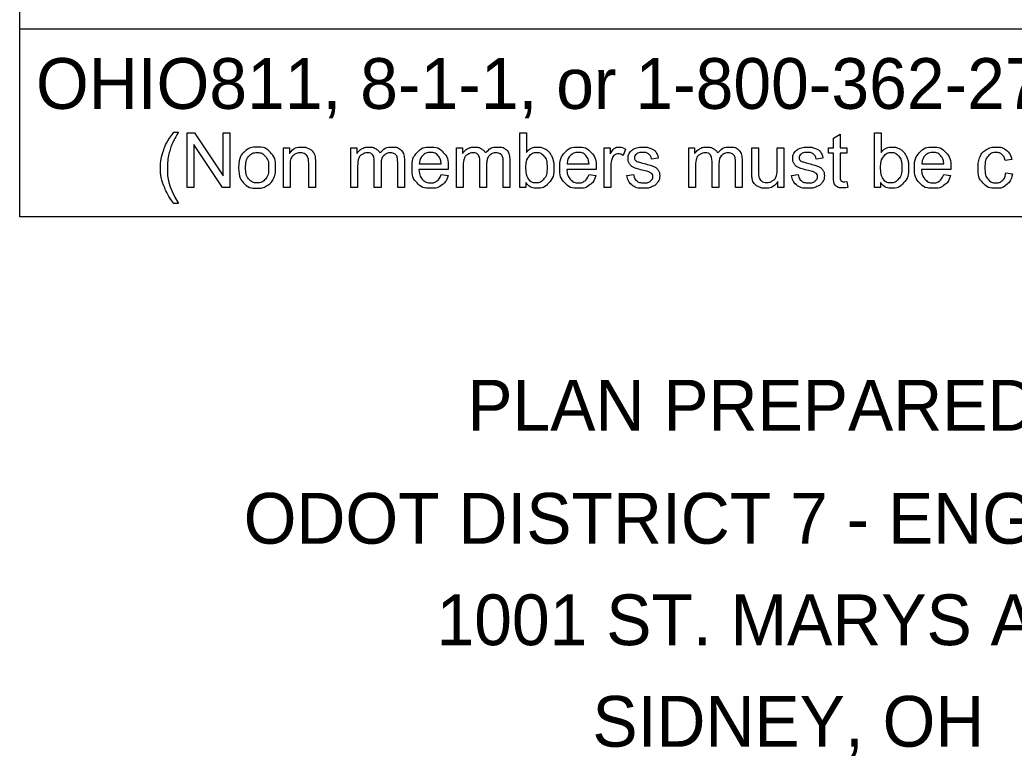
# Model space of a CAD drawing. Extents: x -31.7 to 34, y 0 to 22.
# Drawn here: x -30.869 to -28.125, y 0.655 to 2.686 of the extents above; entities that cross this region are included whole.
import ezdxf

# ---------------------------------------------------------------- set-up
doc = ezdxf.new("R2010")
doc.units = 0
doc.layers.add('SH_Data', color=7, linetype='Continuous')
doc.layers.add('SH_Text', color=7, linetype='Continuous')

msp = doc.modelspace()

# ---------------------------------------------------------------- linework, layer by layer
at = {"layer": 'SH_Data'}
for p, q in [((-30.8694, 2.1428), (-30.8694, 4.4803)), ((-26.6194, 2.6607), (-30.8694, 2.6607)), ((-26.6194, 2.1428), (-30.8694, 2.1428))]:
    msp.add_line(p, q, dxfattribs=at)
at = {"layer": 'SH_Text'}
for points in [[(-30.4447, 2.3766), (-30.4316, 2.3766)], [(-30.408, 2.2239), (-30.408, 2.3741), (-30.3877, 2.3741), (-30.3087, 2.2561), (-30.3087, 2.3741), (-30.2897, 2.3741), (-30.2897, 2.2239), (-30.31, 2.2239), (-30.389, 2.3419), (-30.389, 2.2239), (-30.408, 2.2239)], [(-29.4725, 2.2239), (-29.4896, 2.2239), (-29.4896, 2.3741), (-29.4712, 2.3741), (-29.4712, 2.3206)], [(-28.6236, 2.2558), (-28.6236, 2.3185), (-28.6372, 2.3185), (-28.6372, 2.3328), (-28.6236, 2.3328), (-28.6236, 2.3597), (-28.6052, 2.3708), (-28.6052, 2.3328), (-28.5867, 2.3328), (-28.5867, 2.3185), (-28.6052, 2.3185), (-28.6052, 2.2547)], [(-28.4935, 2.2239), (-28.5105, 2.2239), (-28.5105, 2.3741), (-28.4921, 2.3741), (-28.4921, 2.3206)], [(-30.142, 2.2239), (-30.142, 2.3328), (-30.1254, 2.3328), (-30.1254, 2.3173)], [(-29.9556, 2.2239), (-29.9556, 2.3328), (-29.9391, 2.3328), (-29.9391, 2.3174)], [(-29.6643, 2.2239), (-29.6643, 2.3328), (-29.6478, 2.3328), (-29.6478, 2.3174)], [(-29.2565, 2.2239), (-29.2565, 2.3328), (-29.2399, 2.3328), (-29.2399, 2.3163)], [(-29.0233, 2.2239), (-29.0233, 2.3328), (-29.0068, 2.3328), (-29.0068, 2.3174)], [(-28.8489, 2.2654), (-28.8489, 2.3328), (-28.8305, 2.3328), (-28.8305, 2.2724)], [(-28.7792, 2.2745), (-28.7792, 2.3328), (-28.7608, 2.3328), (-28.7608, 2.2239), (-28.7773, 2.2239)], [(-29.1974, 2.3293), (-29.2039, 2.3122)], [(-30.1236, 2.2833), (-30.1236, 2.2239), (-30.142, 2.2239)], [(-30.0537, 2.2908), (-30.0537, 2.2239), (-30.0721, 2.2239), (-30.0721, 2.2901)], [(-29.9372, 2.2803), (-29.9372, 2.2239), (-29.9556, 2.2239)], [(-29.8725, 2.2871), (-29.8725, 2.2239), (-29.891, 2.2239), (-29.891, 2.2946)], [(-29.8081, 2.2986), (-29.8081, 2.2239), (-29.8265, 2.2239), (-29.8265, 2.2924)], [(-29.767, 2.2887), (-29.7062, 2.2887)], [(-29.6458, 2.2803), (-29.6458, 2.2239), (-29.6643, 2.2239)], [(-29.5812, 2.2871), (-29.5812, 2.2239), (-29.5996, 2.2239), (-29.5996, 2.2946)], [(-29.5167, 2.2986), (-29.5167, 2.2239), (-29.5352, 2.2239), (-29.5352, 2.2924)], [(-29.359, 2.2887), (-29.2982, 2.2887)], [(-29.238, 2.2809), (-29.238, 2.2239), (-29.2565, 2.2239)], [(-29.1075, 2.3046), (-29.1255, 2.3022)], [(-29.0048, 2.2803), (-29.0048, 2.2239), (-29.0233, 2.2239)], [(-28.9402, 2.2871), (-28.9402, 2.2239), (-28.9586, 2.2239), (-28.9586, 2.2946)], [(-28.8757, 2.2986), (-28.8757, 2.2239), (-28.8942, 2.2239), (-28.8942, 2.2924)], [(-28.6529, 2.3046), (-28.671, 2.3022)], [(-28.3799, 2.2887), (-28.3192, 2.2887)], [(-28.1315, 2.3007), (-28.1495, 2.298)], [(-29.6869, 2.2736), (-29.768, 2.2736)], [(-29.7064, 2.2591), (-29.6874, 2.2567)], [(-29.2789, 2.2736), (-29.36, 2.2736)], [(-29.2984, 2.2591), (-29.2794, 2.2567)], [(-29.1939, 2.2564), (-29.1757, 2.2593)], [(-28.7393, 2.2564), (-28.7211, 2.2593)], [(-28.2998, 2.2736), (-28.381, 2.2736)], [(-28.3194, 2.2591), (-28.3003, 2.2567)], [(-28.1479, 2.2638), (-28.1298, 2.2613)], [(-29.4725, 2.2375), (-29.4725, 2.2239)], [(-28.7773, 2.2239), (-28.7773, 2.24)], [(-28.5867, 2.2404), (-28.5841, 2.2241)], [(-28.4935, 2.2375), (-28.4935, 2.2239)], [(-30.4316, 2.1798), (-30.4447, 2.1798)]]:
    msp.add_lwpolyline(points, dxfattribs=at)
for points in [[(-30.4447, 2.1798), (-30.46, 2.199), (-30.4706, 2.2248), (-30.4811, 2.2506), (-30.4811, 2.2783), (-30.4811, 2.3026), (-30.4732, 2.325), (-30.464, 2.3509), (-30.4447, 2.3766)], [(-30.4316, 2.3766), (-30.4439, 2.3553), (-30.4479, 2.3462), (-30.4542, 2.332), (-30.4577, 2.3167), (-30.4621, 2.2975), (-30.4621, 2.2782), (-30.4621, 2.2289), (-30.4316, 2.1798)], [(-30.2655, 2.2783), (-30.2655, 2.3085), (-30.2487, 2.3231), (-30.2347, 2.3352), (-30.2145, 2.3352), (-30.1921, 2.3352), (-30.1779, 2.3205), (-30.1637, 2.3058), (-30.1637, 2.2799), (-30.1637, 2.2589), (-30.17, 2.2469), (-30.1763, 2.2348), (-30.1883, 2.2282), (-30.2003, 2.2215), (-30.2145, 2.2215), (-30.2374, 2.2215), (-30.2514, 2.2362), (-30.2655, 2.2508), (-30.2655, 2.2783)], [(-30.1254, 2.3173), (-30.1135, 2.3352), (-30.0908, 2.3352), (-30.081, 2.3352), (-30.0728, 2.3316), (-30.0645, 2.3281), (-30.0604, 2.3224), (-30.0563, 2.3166), (-30.0547, 2.3087), (-30.0537, 2.3036), (-30.0537, 2.2908)], [(-29.9391, 2.3174), (-29.934, 2.3254), (-29.9255, 2.3303), (-29.917, 2.3352), (-29.9061, 2.3352), (-29.8941, 2.3352), (-29.8863, 2.3301), (-29.8786, 2.3251), (-29.8754, 2.3161), (-29.8625, 2.3352), (-29.8418, 2.3352), (-29.8255, 2.3352), (-29.8168, 2.3262), (-29.8081, 2.3172), (-29.8081, 2.2986)], [(-29.6874, 2.2567), (-29.6919, 2.24), (-29.7041, 2.2307), (-29.7163, 2.2215), (-29.7352, 2.2215), (-29.7591, 2.2215), (-29.7731, 2.2362), (-29.787, 2.2509), (-29.787, 2.2774), (-29.787, 2.3049), (-29.7729, 2.32), (-29.7588, 2.3352), (-29.7362, 2.3352), (-29.7144, 2.3352), (-29.7006, 2.3203), (-29.6868, 2.3055), (-29.6868, 2.2785), (-29.6868, 2.2769), (-29.6869, 2.2736)], [(-29.6478, 2.3174), (-29.6426, 2.3254), (-29.6341, 2.3303), (-29.6256, 2.3352), (-29.6148, 2.3352), (-29.6027, 2.3352), (-29.5949, 2.3301), (-29.5872, 2.3251), (-29.584, 2.3161), (-29.5711, 2.3352), (-29.5504, 2.3352), (-29.5342, 2.3352), (-29.5255, 2.3262), (-29.5167, 2.3172), (-29.5167, 2.2986)], [(-29.4712, 2.3206), (-29.4595, 2.3352), (-29.4414, 2.3352), (-29.4313, 2.3352), (-29.4224, 2.3311), (-29.4134, 2.3271), (-29.4076, 2.3198), (-29.4018, 2.3124), (-29.3986, 2.3021), (-29.3953, 2.2918), (-29.3953, 2.28), (-29.3953, 2.252), (-29.4091, 2.2368), (-29.423, 2.2215), (-29.4423, 2.2215), (-29.4616, 2.2215), (-29.4725, 2.2375)], [(-29.2794, 2.2567), (-29.2839, 2.24), (-29.2961, 2.2307), (-29.3083, 2.2215), (-29.3272, 2.2215), (-29.3511, 2.2215), (-29.3651, 2.2362), (-29.379, 2.2509), (-29.379, 2.2774), (-29.379, 2.3049), (-29.3649, 2.32), (-29.3508, 2.3352), (-29.3282, 2.3352), (-29.3064, 2.3352), (-29.2926, 2.3203), (-29.2788, 2.3055), (-29.2788, 2.2785), (-29.2788, 2.2769), (-29.2789, 2.2736)], [(-29.2399, 2.3163), (-29.2335, 2.3278), (-29.2282, 2.3315), (-29.2228, 2.3352), (-29.2163, 2.3352), (-29.207, 2.3352), (-29.1974, 2.3293)], [(-29.1757, 2.2593), (-29.1741, 2.2483), (-29.1671, 2.2425), (-29.1601, 2.2366), (-29.1474, 2.2366), (-29.1347, 2.2366), (-29.1285, 2.2418), (-29.1223, 2.247), (-29.1223, 2.254), (-29.1223, 2.2602), (-29.1278, 2.2638), (-29.1316, 2.2663), (-29.1467, 2.2701), (-29.167, 2.2752), (-29.1748, 2.2789), (-29.1827, 2.2827), (-29.1867, 2.2893), (-29.1908, 2.2959), (-29.1908, 2.3038), (-29.1908, 2.3111), (-29.1874, 2.3173), (-29.1841, 2.3235), (-29.1784, 2.3276), (-29.1741, 2.3308), (-29.1666, 2.333), (-29.1592, 2.3352), (-29.1507, 2.3352), (-29.1378, 2.3352), (-29.1281, 2.3315), (-29.1184, 2.3278), (-29.1138, 2.3215), (-29.1092, 2.3152), (-29.1075, 2.3046)], [(-29.0068, 2.3174), (-29.0016, 2.3254), (-28.9931, 2.3303), (-28.9846, 2.3352), (-28.9738, 2.3352), (-28.9617, 2.3352), (-28.9539, 2.3301), (-28.9462, 2.3251), (-28.943, 2.3161), (-28.9301, 2.3352), (-28.9094, 2.3352), (-28.8932, 2.3352), (-28.8845, 2.3262), (-28.8757, 2.3172), (-28.8757, 2.2986)], [(-28.7211, 2.2593), (-28.7196, 2.2483), (-28.7125, 2.2425), (-28.7055, 2.2366), (-28.6928, 2.2366), (-28.6801, 2.2366), (-28.6739, 2.2418), (-28.6678, 2.247), (-28.6678, 2.254), (-28.6678, 2.2602), (-28.6732, 2.2638), (-28.677, 2.2663), (-28.6921, 2.2701), (-28.7124, 2.2752), (-28.7203, 2.2789), (-28.7281, 2.2827), (-28.7322, 2.2893), (-28.7362, 2.2959), (-28.7362, 2.3038), (-28.7362, 2.3111), (-28.7329, 2.3173), (-28.7295, 2.3235), (-28.7238, 2.3276), (-28.7195, 2.3308), (-28.712, 2.333), (-28.7046, 2.3352), (-28.6961, 2.3352), (-28.6833, 2.3352), (-28.6736, 2.3315), (-28.6639, 2.3278), (-28.6593, 2.3215), (-28.6546, 2.3152), (-28.6529, 2.3046)], [(-28.4921, 2.3206), (-28.4804, 2.3352), (-28.4623, 2.3352), (-28.4523, 2.3352), (-28.4433, 2.3311), (-28.4343, 2.3271), (-28.4286, 2.3198), (-28.4228, 2.3124), (-28.4195, 2.3021), (-28.4162, 2.2918), (-28.4162, 2.28), (-28.4162, 2.252), (-28.4301, 2.2368), (-28.4439, 2.2215), (-28.4632, 2.2215), (-28.4825, 2.2215), (-28.4935, 2.2375)], [(-28.3003, 2.2567), (-28.3048, 2.24), (-28.317, 2.2307), (-28.3292, 2.2215), (-28.3482, 2.2215), (-28.372, 2.2215), (-28.386, 2.2362), (-28.4, 2.2509), (-28.4, 2.2774), (-28.4, 2.3049), (-28.3858, 2.32), (-28.3717, 2.3352), (-28.3492, 2.3352), (-28.3274, 2.3352), (-28.3135, 2.3203), (-28.2997, 2.3055), (-28.2997, 2.2785), (-28.2997, 2.2769), (-28.2998, 2.2736)], [(-28.1298, 2.2613), (-28.1327, 2.2427), (-28.145, 2.2321), (-28.1572, 2.2215), (-28.1751, 2.2215), (-28.1974, 2.2215), (-28.211, 2.2361), (-28.2245, 2.2507), (-28.2245, 2.2779), (-28.2245, 2.2955), (-28.2187, 2.3088), (-28.2128, 2.322), (-28.2009, 2.3286), (-28.189, 2.3352), (-28.1749, 2.3352), (-28.1572, 2.3352), (-28.1459, 2.3262), (-28.1347, 2.3172), (-28.1315, 2.3007)], [(-30.2465, 2.2783), (-30.2465, 2.2574), (-30.2374, 2.247), (-30.2283, 2.2366), (-30.2145, 2.2366), (-30.2008, 2.2366), (-30.1918, 2.2471), (-30.1827, 2.2575), (-30.1827, 2.279), (-30.1827, 2.2991), (-30.1918, 2.3095), (-30.201, 2.3199), (-30.2145, 2.3199), (-30.2283, 2.3199), (-30.2374, 2.3096), (-30.2465, 2.2992), (-30.2465, 2.2783)], [(-30.0721, 2.2901), (-30.0721, 2.3013), (-30.0743, 2.3069), (-30.0764, 2.3125), (-30.0819, 2.3158), (-30.0874, 2.3191), (-30.0947, 2.3191), (-30.1065, 2.3191), (-30.1151, 2.3117), (-30.1236, 2.3042), (-30.1236, 2.2833)], [(-29.891, 2.2946), (-29.891, 2.3069), (-29.8955, 2.313), (-29.9, 2.3191), (-29.9102, 2.3191), (-29.918, 2.3191), (-29.9246, 2.315), (-29.9313, 2.311), (-29.9342, 2.3031), (-29.9372, 2.2952), (-29.9372, 2.2803)], [(-29.8265, 2.2924), (-29.8265, 2.3035), (-29.8283, 2.3083), (-29.8301, 2.3132), (-29.8348, 2.3162), (-29.8395, 2.3191), (-29.8459, 2.3191), (-29.8574, 2.3191), (-29.865, 2.3115), (-29.8725, 2.3039), (-29.8725, 2.2871)], [(-29.7062, 2.2887), (-29.7075, 2.3025), (-29.7132, 2.3094), (-29.722, 2.3201), (-29.7361, 2.3201), (-29.7488, 2.3201), (-29.7574, 2.3115), (-29.7661, 2.303), (-29.767, 2.2887)], [(-29.5996, 2.2946), (-29.5996, 2.3069), (-29.6041, 2.313), (-29.6086, 2.3191), (-29.6189, 2.3191), (-29.6267, 2.3191), (-29.6333, 2.315), (-29.6399, 2.311), (-29.6429, 2.3031), (-29.6458, 2.2952), (-29.6458, 2.2803)], [(-29.5352, 2.2924), (-29.5352, 2.3035), (-29.537, 2.3083), (-29.5387, 2.3132), (-29.5435, 2.3162), (-29.5482, 2.3191), (-29.5545, 2.3191), (-29.566, 2.3191), (-29.5736, 2.3115), (-29.5812, 2.3039), (-29.5812, 2.2871)], [(-29.4728, 2.2792), (-29.4728, 2.2596), (-29.4675, 2.2509), (-29.4588, 2.2366), (-29.4439, 2.2366), (-29.4319, 2.2366), (-29.4231, 2.2471), (-29.4143, 2.2576), (-29.4143, 2.2784), (-29.4143, 2.2998), (-29.4227, 2.3099), (-29.4312, 2.3201), (-29.4431, 2.3201), (-29.4552, 2.3201), (-29.464, 2.3096), (-29.4728, 2.299), (-29.4728, 2.2792)], [(-29.2982, 2.2887), (-29.2995, 2.3025), (-29.3052, 2.3094), (-29.314, 2.3201), (-29.3281, 2.3201), (-29.3408, 2.3201), (-29.3494, 2.3115), (-29.3581, 2.303), (-29.359, 2.2887)], [(-29.2039, 2.3122), (-29.2106, 2.3162), (-29.2173, 2.3162), (-29.2233, 2.3162), (-29.2281, 2.3125), (-29.2329, 2.3089), (-29.235, 2.3024), (-29.238, 2.2926), (-29.238, 2.2809)], [(-29.1255, 2.3022), (-29.1268, 2.3106), (-29.1327, 2.3153), (-29.1386, 2.3201), (-29.1493, 2.3201), (-29.1621, 2.3201), (-29.1675, 2.3159), (-29.1729, 2.3116), (-29.1729, 2.306), (-29.1729, 2.3024), (-29.1707, 2.2995), (-29.1684, 2.2966), (-29.1636, 2.2946), (-29.1608, 2.2936), (-29.1473, 2.2899), (-29.1277, 2.2847), (-29.1199, 2.2813), (-29.1122, 2.278), (-29.1078, 2.2717), (-29.1033, 2.2653), (-29.1033, 2.2559), (-29.1033, 2.2467), (-29.1087, 2.2386), (-29.1141, 2.2304), (-29.1243, 2.226), (-29.1344, 2.2215), (-29.1473, 2.2215), (-29.1685, 2.2215), (-29.1797, 2.2303), (-29.1908, 2.2391), (-29.1939, 2.2564)], [(-28.9586, 2.2946), (-28.9586, 2.3069), (-28.9631, 2.313), (-28.9676, 2.3191), (-28.9779, 2.3191), (-28.9857, 2.3191), (-28.9923, 2.315), (-28.9989, 2.311), (-29.0019, 2.3031), (-29.0048, 2.2952), (-29.0048, 2.2803)], [(-28.8942, 2.2924), (-28.8942, 2.3035), (-28.896, 2.3083), (-28.8977, 2.3132), (-28.9025, 2.3162), (-28.9072, 2.3191), (-28.9135, 2.3191), (-28.925, 2.3191), (-28.9326, 2.3115), (-28.9402, 2.3039), (-28.9402, 2.2871)], [(-28.671, 2.3022), (-28.6722, 2.3106), (-28.6781, 2.3153), (-28.684, 2.3201), (-28.6948, 2.3201), (-28.7075, 2.3201), (-28.7129, 2.3159), (-28.7184, 2.3116), (-28.7184, 2.306), (-28.7184, 2.3024), (-28.7161, 2.2995), (-28.7138, 2.2966), (-28.709, 2.2946), (-28.7063, 2.2936), (-28.6927, 2.2899), (-28.6731, 2.2847), (-28.6654, 2.2813), (-28.6576, 2.278), (-28.6532, 2.2717), (-28.6488, 2.2653), (-28.6488, 2.2559), (-28.6488, 2.2467), (-28.6542, 2.2386), (-28.6596, 2.2304), (-28.6697, 2.226), (-28.6799, 2.2215), (-28.6927, 2.2215), (-28.7139, 2.2215), (-28.7251, 2.2303), (-28.7362, 2.2391), (-28.7393, 2.2564)], [(-28.4937, 2.2792), (-28.4937, 2.2596), (-28.4884, 2.2509), (-28.4797, 2.2366), (-28.4649, 2.2366), (-28.4528, 2.2366), (-28.444, 2.2471), (-28.4352, 2.2576), (-28.4352, 2.2784), (-28.4352, 2.2998), (-28.4437, 2.3099), (-28.4521, 2.3201), (-28.4641, 2.3201), (-28.4761, 2.3201), (-28.4849, 2.3096), (-28.4937, 2.299), (-28.4937, 2.2792)], [(-28.3192, 2.2887), (-28.3204, 2.3025), (-28.3261, 2.3094), (-28.335, 2.3201), (-28.349, 2.3201), (-28.3617, 2.3201), (-28.3704, 2.3115), (-28.379, 2.303), (-28.3799, 2.2887)], [(-28.1495, 2.298), (-28.152, 2.309), (-28.1585, 2.3145), (-28.165, 2.3201), (-28.1742, 2.3201), (-28.1881, 2.3201), (-28.1968, 2.3101), (-28.2055, 2.3001), (-28.2055, 2.2784), (-28.2055, 2.2565), (-28.1971, 2.2466), (-28.1887, 2.2366), (-28.1752, 2.2366), (-28.1643, 2.2366), (-28.1571, 2.2433), (-28.1498, 2.2499), (-28.1479, 2.2638)], [(-29.768, 2.2736), (-29.767, 2.2557), (-29.7579, 2.2462), (-29.7488, 2.2366), (-29.7351, 2.2366), (-29.725, 2.2366), (-29.7178, 2.242), (-29.7106, 2.2473), (-29.7064, 2.2591)], [(-29.36, 2.2736), (-29.359, 2.2557), (-29.3499, 2.2462), (-29.3408, 2.2366), (-29.3271, 2.2366), (-29.317, 2.2366), (-29.3098, 2.242), (-29.3026, 2.2473), (-29.2984, 2.2591)], [(-28.7773, 2.24), (-28.79, 2.2215), (-28.8118, 2.2215), (-28.8214, 2.2215), (-28.8297, 2.2252), (-28.8381, 2.2289), (-28.8421, 2.2345), (-28.8462, 2.2401), (-28.8478, 2.2482), (-28.8489, 2.2536), (-28.8489, 2.2654)], [(-28.8305, 2.2724), (-28.8305, 2.258), (-28.8294, 2.253), (-28.8276, 2.2457), (-28.822, 2.2416), (-28.8164, 2.2374), (-28.8081, 2.2374), (-28.7998, 2.2374), (-28.7925, 2.2417), (-28.7853, 2.2459), (-28.7823, 2.2533), (-28.7792, 2.2606), (-28.7792, 2.2745)], [(-28.5841, 2.2241), (-28.5919, 2.2224), (-28.598, 2.2224), (-28.608, 2.2224), (-28.6136, 2.2256), (-28.6191, 2.2288), (-28.6213, 2.234), (-28.6236, 2.2392), (-28.6236, 2.2558)], [(-28.6052, 2.2547), (-28.6052, 2.2468), (-28.6042, 2.2445), (-28.6032, 2.2423), (-28.601, 2.2409), (-28.5989, 2.2396), (-28.5948, 2.2396), (-28.5917, 2.2396), (-28.5867, 2.2404)], [(-28.381, 2.2736), (-28.38, 2.2557), (-28.3708, 2.2462), (-28.3617, 2.2366), (-28.3481, 2.2366), (-28.3379, 2.2366), (-28.3308, 2.242), (-28.3236, 2.2473), (-28.3194, 2.2591)]]:
    msp.add_open_spline(points, degree=3, dxfattribs=at)

# ---------------------------------------------------------------- texts
for s, p in [('OHIO811, 8-1-1, or 1-800-362-2764', (-30.8249, 2.4406)), ('PLAN PREPARED BY:', (-29.6344, 1.553)), ('ODOT DISTRICT 7 - ENGINEERING ', (-30.2516, 1.241)), ('1001 ST. MARYS AVE. ', (-29.7194, 0.961)), ('SIDNEY, OH ', (-29.2891, 0.681))]:
    msp.add_text(s, height=0.14, dxfattribs=at).set_placement(p)

doc.saveas('drawing.dxf')
